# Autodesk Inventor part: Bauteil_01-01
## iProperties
Created: 2007-04
Part Number: Bauteil_01-01
Document SubType Name: Modeling
Designer: Sascha Fleischer
Author: Sascha Fleischer
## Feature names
1. Abgeleiteter Körper1 [Tagging]
